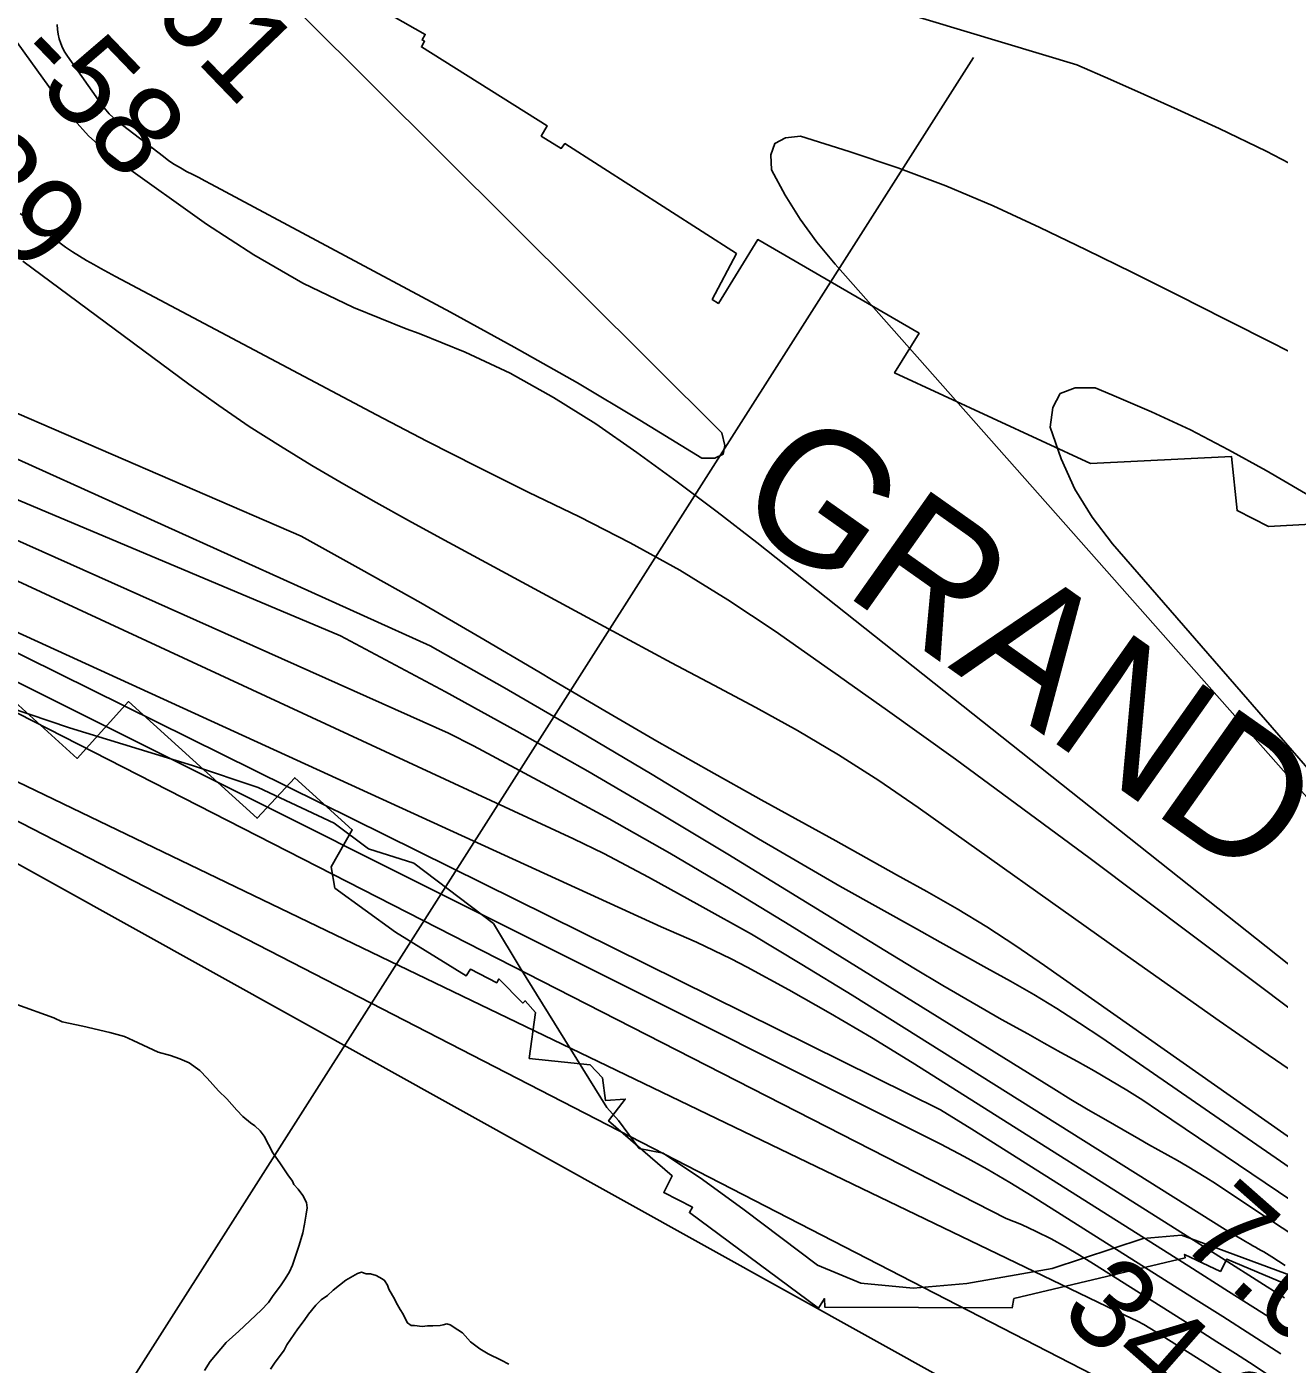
# Model space of a CAD drawing. Extents: x 3263578 to 3301413, y 764927 to 798602.
# Drawn here: x 3278134 to 3279070, y 785102 to 786102 of the extents above; entities that cross this region are included whole.
import ezdxf

# ---------------------------------------------------------------- set-up
doc = ezdxf.new("R2010")
doc.units = 0
for name, color, linetype in [('V-RIVR-EDGE', 7, 'Continuous'), ('V-RIVR-RANG', 7, 'Continuous'), ('V-RRAP-RVMT', 7, 'Continuous'), ('V-RRAP-RVMT-IDEN', 7, 'Continuous'), ('V-SITE-VEGE', 7, 'Continuous'), ('V-TOPO-DPTH', 7, 'Continuous'), ('V-TOPO-MAJR', 7, 'Continuous'), ('V-TOPO-MINR', 7, 'Continuous'), ('V-TOPO-WATR', 7, 'Continuous')]:
    doc.layers.add(name, color=color, linetype=linetype)

msp = doc.modelspace()

# ---------------------------------------------------------------- linework, layer by layer
at = {"layer": 'V-RIVR-EDGE'}
for points in [[(3278074.7, 785608), (3278165.5, 785577.4), (3278257.6, 785549.3), (3278306.7, 785532.7), (3278363.5, 785506), (3278389.1, 785486.9), (3278423, 785476.3), (3278482.5, 785431), (3278502.4, 785397.9), (3278540.5, 785337), (3278567.3, 785293.4), (3278576, 785283.8), (3278591.6, 785262.9)], [(3278591.6, 785262.9), (3278609.4, 785259.4), (3278638.9, 785239.8), (3278670.1, 785217.1), (3278724.8, 785175.7), (3278757.4, 785162.1), (3278796.5, 785158.5), (3278836.5, 785161.9), (3278900.4, 785173.1), (3278968.3, 785195.5), (3278997, 785198), (3279024.3, 785188), (3279144.2, 785143.8)]]:
    msp.add_lwpolyline(points, dxfattribs=at)
at = {"layer": 'V-RIVR-RANG'}
msp.add_line((3278164.9, 785015.8), (3278841.6, 786078.7), dxfattribs=at)
at = {"layer": 'V-RRAP-RVMT'}
for points in [[(3278375.6, 786127.6), (3278431.5, 786095.9), (3278429.2, 786091.8), (3278431, 786090.8), (3278428.7, 786086.5), (3278522.8, 786027.4), (3278518.3, 786019.9), (3278533.2, 786010.6), (3278536, 786014.2), (3278664.3, 785932), (3278646.2, 785897.7), (3278650.8, 785894.7), (3278680.2, 785942.5), (3278800.8, 785872.4), (3278782.5, 785842.8), (3278929.1, 785775), (3279034.6, 785780.2), (3279038.7, 785739.8), (3279062.1, 785727.9), (3279152.7, 785733)], [(3279091.8, 785154.5), (3279030.9, 785180.2), (3279026.2, 785170.9), (3278999.4, 785183.7), (3278999.9, 785181.2), (3278871.8, 785150.7), (3278870.5, 785143.8), (3278730.4, 785144.2), (3278730, 785150.7), (3278725.7, 785143.5), (3278629.1, 785214.9), (3278631.4, 785218.9), (3278609.9, 785229.9), (3278616.2, 785242.4), (3278568.6, 785283.5), (3278581.1, 785299.8), (3278566.4, 785298.7), (3278564.2, 785315.7), (3278554.8, 785325.3), (3278509.3, 785330.2), (3278514, 785364.5), (3278506.2, 785373.3), (3278504.4, 785371.6), (3278486.6, 785389.7), (3278485, 785386.8), (3278465.3, 785396.9), (3278462.2, 785392), (3278409.4, 785424.7), (3278363.9, 785457.6), (3278361.2, 785473.5), (3278376.9, 785501.2), (3278333.9, 785540.1), (3278305.8, 785509.8), (3278209.6, 785597), (3278171.2, 785554.5), (3278075, 785641.8)]]:
    msp.add_lwpolyline(points, dxfattribs=at)
at = {"layer": 'V-SITE-VEGE'}
for points in [[(3278126.1, 785370.6), (3278153.7, 785360.6), (3278160, 785357.6), (3278175.5, 785354.3), (3278195.7, 785349.7), (3278206.7, 785346.5), (3278213, 785343.5), (3278231.9, 785334.9), (3278241.1, 785332.3), (3278248, 785329.8), (3278254.9, 785326.8), (3278262.9, 785321.3), (3278268.5, 785315.4), (3278277, 785305.9), (3278283.2, 785299.9), (3278290.6, 785291.6), (3278295.1, 785286.9), (3278300.8, 785282.1), (3278304.2, 785279.7), (3278308.2, 785276.1), (3278311, 785272), (3278317.6, 785259.6), (3278323.2, 785251.4), (3278328.8, 785243.1), (3278332.2, 785238.4), (3278333.3, 785236), (3278336.6, 785232.5)], [(3278336.6, 785232.5), (3278340, 785227.8), (3278342.8, 785222.5), (3278343.3, 785218.4), (3278342.6, 785213.8), (3278341.2, 785206.3), (3278339.9, 785199.9), (3278337.3, 785190.7), (3278332.3, 785175.7), (3278329.9, 785170.6), (3278326.8, 785165.4), (3278323.2, 785160.3), (3278317.8, 785152.9), (3278314.2, 785147.8), (3278308.9, 785142.1), (3278292.2, 785126.3), (3278282.7, 785117.8), (3278270.8, 785103.6), (3278266.5, 785096.8)], [(3278315.9, 785097.8), (3278318.9, 785102.4), (3278326.1, 785112.1), (3278327.9, 785116.1), (3278336.3, 785128.1), (3278341.1, 785134.3), (3278344.2, 785138.9), (3278349.6, 785145.7), (3278353.7, 785149.7), (3278358.4, 785153), (3278362.6, 785157), (3278372.1, 785164.3), (3278380.9, 785169.3), (3278383.8, 785170.4), (3278387.3, 785169.1), (3278390.7, 785169.1), (3278394.8, 785167.8), (3278399.4, 785165.4), (3278401.1, 785164.2), (3278403.3, 785160.6), (3278404.4, 785157.7), (3278408.8, 785150), (3278409.9, 785147.7), (3278412.7, 785142.4), (3278414.9, 785138.9), (3278417.1, 785134.7), (3278418.3, 785132.4), (3278421.1, 785130.6), (3278423.4, 785130.5), (3278429.2, 785129.8), (3278433.3, 785130.3), (3278437.3, 785130.2), (3278442.6, 785130.6), (3278444.9, 785131.1), (3278447.8, 785131.7), (3278450.1, 785131), (3278455.8, 785127.4), (3278459.3, 785125), (3278465.5, 785118.4), (3278472.3, 785113.1), (3278478.6, 785109.4), (3278488.3, 785104.5), (3278494, 785101.5)]]:
    msp.add_lwpolyline(points, dxfattribs=at)
at = {"layer": 'V-TOPO-DPTH'}
for points in [[(3278128.7, 785961.9), (3278157.6, 785940.5), (3278162.6, 785936.9), (3278167.7, 785933.4), (3278173, 785930.1), (3278178.3, 785926.9), (3278183.6, 785923.8), (3278189, 785920.8), (3278194.5, 785917.8), (3278199.9, 785914.9), (3278395.1, 785811.5), (3278432.7, 785791.8), (3278470.6, 785772.5), (3278508.6, 785753.6), (3278546.8, 785735.1), (3278584.7, 785715.8), (3278621.8, 785695.4), (3278657.8, 785673.1), (3278693.1, 785649.7), (3278726, 785626.6), (3278777.1, 785590.4), (3278828, 785553.9), (3278878.5, 785516.9), (3278928.7, 785479.6), (3279162.7, 785304)], [(3279162.7, 785304), (3278928.7, 785479.6), (3278878.5, 785516.9), (3278828, 785553.9), (3278777.1, 785590.4), (3278726, 785626.6), (3278693.1, 785649.7), (3278657.8, 785673.1), (3278621.8, 785695.4), (3278584.7, 785715.8), (3278546.8, 785735.1), (3278508.6, 785753.6), (3278470.6, 785772.5), (3278432.7, 785791.8), (3278395.1, 785811.5), (3278199.9, 785914.9), (3278194.5, 785917.8), (3278189, 785920.8), (3278183.6, 785923.8), (3278178.3, 785926.9), (3278173, 785930.1), (3278167.7, 785933.4), (3278162.6, 785936.9), (3278157.6, 785940.5), (3278128.7, 785961.9)], [(3279098.7, 785307.7), (3279062, 785333), (3279025.3, 785358.4), (3278988.8, 785384), (3278952.4, 785409.7), (3278800.1, 785517.9), (3278770.7, 785538), (3278740.7, 785557.2), (3278710, 785575.3), (3278678.8, 785592.6), (3278647.3, 785609.4), (3278615.8, 785626.1), (3278584.4, 785643), (3278552.9, 785659.9), (3278443.2, 785719.2), (3278418.9, 785732.5), (3278394.8, 785745.9), (3278370.7, 785759.6), (3278346.8, 785773.5), (3278323.2, 785787.9), (3278299.9, 785802.7), (3278277.1, 785818.3), (3278254.7, 785834.4), (3278130.7, 785926.4)], [(3279098.7, 785307.7), (3279062, 785333), (3279025.3, 785358.4), (3278988.8, 785384), (3278952.4, 785409.7), (3278800.1, 785517.9), (3278770.7, 785538), (3278740.7, 785557.2), (3278710, 785575.3), (3278678.8, 785592.6), (3278647.3, 785609.4), (3278615.8, 785626.1), (3278584.4, 785643), (3278552.9, 785659.9), (3278443.2, 785719.2), (3278418.9, 785732.5), (3278394.8, 785745.9), (3278370.7, 785759.6), (3278346.8, 785773.5), (3278323.2, 785787.9), (3278299.9, 785802.7), (3278277.1, 785818.3), (3278254.7, 785834.4), (3278130.7, 785926.4)], [(3278020.5, 785858.4), (3278338.7, 785720.6), (3278383.6, 785695.9), (3278428.2, 785670.9), (3278472.4, 785645.3), (3278516.5, 785619.3), (3278527.3, 785612.8), (3278565.9, 785590), (3278604.6, 785567.5), (3278643.6, 785545.4), (3278682.8, 785523.5), (3278715.8, 785505.4), (3278738.5, 785492.9), (3278761.3, 785480.3), (3278784, 785467.6), (3278806.7, 785455), (3278829.2, 785442), (3278851.4, 785428.5), (3278873.2, 785414.4), (3278894.7, 785399.8), (3279137.2, 785229.4)], [(3278020.5, 785858.4), (3278338.7, 785720.6), (3278383.6, 785695.9), (3278428.2, 785670.9), (3278472.4, 785645.3), (3278516.5, 785619.3), (3278527.3, 785612.8), (3278565.9, 785590), (3278604.6, 785567.5), (3278643.6, 785545.4), (3278682.8, 785523.5), (3278715.8, 785505.4), (3278738.5, 785492.9), (3278761.3, 785480.3), (3278784, 785467.6), (3278806.7, 785455), (3278829.2, 785442), (3278851.4, 785428.5), (3278873.2, 785414.4), (3278894.7, 785399.8), (3279137.2, 785229.4)], [(3279079.6, 785223.8), (3278979.9, 785291.1), (3278968.1, 785298.9), (3278956.1, 785306.5), (3278944, 785313.8), (3278931.7, 785320.9), (3278919.3, 785327.8), (3278906.9, 785334.7), (3278894.5, 785341.6), (3278882.1, 785348.5), (3278862.6, 785359.4), (3278840.6, 785372), (3278818.6, 785384.7), (3278796.8, 785397.6), (3278775.2, 785410.8), (3278657.7, 785482.9), (3278605.5, 785514.3), (3278553, 785545.1), (3278500, 785574.9), (3278446.6, 785604.2), (3278368.2, 785646.2), (3277976.7, 785810.9)], [(3279079.6, 785223.8), (3278979.9, 785291.1), (3278968.1, 785298.9), (3278956.1, 785306.5), (3278944, 785313.8), (3278931.7, 785320.9), (3278919.3, 785327.8), (3278906.9, 785334.7), (3278894.5, 785341.6), (3278882.1, 785348.5), (3278862.6, 785359.4), (3278840.6, 785372), (3278818.6, 785384.7), (3278796.8, 785397.6), (3278775.2, 785410.8), (3278657.7, 785482.9), (3278605.5, 785514.3), (3278553, 785545.1), (3278500, 785574.9), (3278446.6, 785604.2), (3278368.2, 785646.2), (3277976.7, 785810.9)], [(3277930.9, 785777.7), (3278542.5, 785494.5), (3278565, 785483.4), (3278598.4, 785465.7), (3278637, 785444.6), (3278675.4, 785423), (3278713.2, 785400.5), (3278750.8, 785377.5), (3279029.8, 785202.3), (3279033.5, 785200), (3279037.3, 785197.8), (3279041.1, 785195.5), (3279044.9, 785193.3), (3279048.4, 785191.4), (3279050.4, 785190.2), (3279052.5, 785189), (3279054.5, 785187.9), (3279056.6, 785186.7), (3279058.7, 785185.5), (3279060.7, 785184.3), (3279062.7, 785183.1), (3279064.7, 785181.8), (3279074.5, 785175.5)], [(3277930.9, 785777.7), (3278542.5, 785494.5), (3278565, 785483.4), (3278598.4, 785465.7), (3278637, 785444.6), (3278675.4, 785423), (3278713.2, 785400.5), (3278750.8, 785377.5), (3279029.8, 785202.3), (3279033.5, 785200), (3279037.3, 785197.8), (3279041.1, 785195.5), (3279044.9, 785193.3), (3279048.4, 785191.4), (3279050.4, 785190.2), (3279052.5, 785189), (3279054.5, 785187.9), (3279056.6, 785186.7), (3279058.7, 785185.5), (3279060.7, 785184.3), (3279062.7, 785183.1), (3279064.7, 785181.8), (3279074.5, 785175.5)], [(3280108.8, 784602.6), (3280105.1, 784605.7), (3280097, 784612), (3280088.7, 784618), (3280032.8, 784656.3), (3280020.2, 784664.7), (3280007.6, 784672.8), (3279994.7, 784680.5), (3279981.7, 784688.1), (3279968.5, 784695.3), (3279955.3, 784702.4), (3279941.9, 784709.3), (3279928.5, 784716.1), (3279905.2, 784727.6), (3279879.7, 784739.3), (3279174.8, 785064.2), (3279120.7, 785099.3), (3279091.3, 785118.3), (3279061.8, 785137.2), (3279032.2, 785156), (3279002.6, 785174.8), (3278840.2, 785277.4), (3278816.8, 785291.7), (3277913, 785738.9)]]:
    msp.add_lwpolyline(points, dxfattribs=at)
at = {"layer": 'V-TOPO-MAJR'}
for points in [[(3279536.3, 785673.9), (3279530.6, 785678), (3279525, 785682.1), (3279289.2, 785861), (3279257.9, 785884.2), (3279226.3, 785906.9), (3279194.1, 785929), (3279161.7, 785950.6), (3279128.6, 785971.1), (3279094.9, 785990.6), (3279060.4, 786008.5), (3279025.3, 786025.5), (3278994.2, 786039.7), (3278969.2, 786051), (3278944, 786062.2), (3278918.8, 786073.2), (3278419.2, 786223.7)], [(3278044, 786204.1), (3278158.9, 786044.5), (3278169, 786031.9), (3278179.8, 786020), (3278191.7, 786009.3), (3278204.4, 785999.3), (3278267.9, 785954.1), (3278303.3, 785931), (3278339.9, 785909.9), (3278378, 785891.8), (3278417.2, 785875.8), (3278426.9, 785872.3), (3278461.4, 785858.4), (3278495.1, 785842.7), (3278527.5, 785824.5), (3278559, 785804.7), (3278589.7, 785783.3), (3278620, 785761.4), (3278649.9, 785738.9), (3278679.5, 785715.9), (3279192.9, 785308.7)], [(3277841.3, 785674.3), (3278954.6, 785138.3), (3278959.4, 785136.1), (3278964.1, 785133.7), (3278968.8, 785131.2), (3278973.4, 785128.5), (3278978, 785125.7), (3279013, 785103.6), (3279019.2, 785099.6), (3279025.4, 785095.7), (3279031.5, 785091.7), (3279037.7, 785087.7), (3279961.1, 784591.1), (3280018.6, 784566.2), (3280039, 784555.3), (3280049.3, 784548.2)]]:
    msp.add_lwpolyline(points, dxfattribs=at)
at = {"layer": 'V-TOPO-MINR'}
for points in [[(3276581.6, 787830.9), (3276665.1, 787735.6), (3277232.8, 786656.4), (3277234.3, 786653.6), (3277235.7, 786650.8), (3277237.2, 786648), (3277238.7, 786645.3), (3277793.7, 785682.2), (3277809, 785664.6), (3277825.7, 785648.5), (3277843.3, 785633.3), (3278947.3, 785019.5), (3278951.5, 785017.8), (3278955.6, 785015.9), (3278959.7, 785013.8), (3278963.6, 785011.4), (3280019.9, 784521.3)], [(3278244.1, 785998.6), (3278248.6, 785996), (3278253.1, 785993.5), (3278257.7, 785991.2), (3278262.3, 785988.9), (3278266.8, 785986.5), (3278271.4, 785984), (3278450.5, 785888.2), (3278498.1, 785862.1), (3278545.3, 785835.3), (3278592, 785807.5), (3278638.3, 785779.1), (3278648, 785779.1), (3278654.3, 785781.9), (3278655.5, 785788.6), (3278653.3, 785798), (3278339.6, 786110.3)], [(3278156.2, 786103.2), (3278156.5, 786099.6), (3278157, 786096), (3278157.8, 786092.5), (3278158.9, 786089.1), (3278160.3, 786085.8), (3278162, 786082.6), (3278163.9, 786079.6), (3278190.2, 786042.5), (3278192.6, 786039.4), (3278195.2, 786036.5), (3278198.1, 786033.8), (3278201, 786031.3), (3278235.7, 786004.5), (3278239.9, 786001.4), (3278244.1, 785998.6)], [(3279100.9, 785846.8), (3279065.9, 785864.7), (3279030.8, 785882.5), (3279029.2, 785883.3), (3278994.8, 785900.6), (3278960.4, 785917.8), (3278925.8, 785934.8), (3278891.2, 785951.6), (3278856.3, 785967.6), (3278820.9, 785982.6), (3278784.9, 785996), (3278748.5, 786008.4), (3278712.2, 786019.9), (3278700.9, 786018.6), (3278692.9, 786014.4), (3278690, 786005.9), (3278690.5, 785994.5), (3278700.7, 785975.8), (3278711.9, 785957.7), (3278724.5, 785940.6), (3278738, 785924.1), (3279215.2, 785385)], [(3278128.7, 785961.9), (3278157.6, 785940.5), (3278162.6, 785936.9), (3278167.7, 785933.4), (3278173, 785930.1), (3278178.3, 785926.9), (3278183.6, 785923.8), (3278189, 785920.8), (3278194.5, 785917.8), (3278199.9, 785914.9), (3278395.1, 785811.5), (3278432.7, 785791.8), (3278470.6, 785772.5), (3278508.6, 785753.6), (3278546.8, 785735.1), (3278584.7, 785715.8), (3278621.8, 785695.4), (3278657.8, 785673.1), (3278693.1, 785649.7), (3278726, 785626.6), (3278777.1, 785590.4), (3278828, 785553.9), (3278878.5, 785516.9), (3278928.7, 785479.6), (3279162.7, 785304)], [(3278130.7, 785926.4), (3278254.7, 785834.4), (3278277.1, 785818.3), (3278299.9, 785802.7), (3278323.2, 785787.9), (3278346.8, 785773.5), (3278370.7, 785759.6), (3278394.8, 785745.9), (3278418.9, 785732.5), (3278443.2, 785719.2), (3278552.9, 785659.9), (3278584.4, 785643), (3278615.8, 785626.1), (3278647.3, 785609.4), (3278678.8, 785592.6), (3278710, 785575.3), (3278740.7, 785557.2), (3278770.7, 785538), (3278800.1, 785517.9), (3278952.4, 785409.7), (3278988.8, 785384), (3279025.3, 785358.4), (3279062, 785333), (3279098.7, 785307.7)], [(3278020.5, 785858.4), (3278338.7, 785720.6), (3278383.6, 785695.9), (3278428.2, 785670.9), (3278472.4, 785645.3), (3278516.5, 785619.3), (3278527.3, 785612.8), (3278565.9, 785590), (3278604.6, 785567.5), (3278643.6, 785545.4), (3278682.8, 785523.5), (3278715.8, 785505.4), (3278738.5, 785492.9), (3278761.3, 785480.3), (3278784, 785467.6), (3278806.7, 785455), (3278829.2, 785442), (3278851.4, 785428.5), (3278873.2, 785414.4), (3278894.7, 785399.8), (3279137.2, 785229.4)], [(3277988.4, 785840.5), (3278435.1, 785638.8), (3278490.9, 785607.4), (3278546.2, 785575.2), (3278601.2, 785542.4), (3278650.4, 785512.6), (3278680.7, 785494.4), (3278711.1, 785476.6), (3278741.7, 785459), (3278772.4, 785441.7), (3278799, 785427), (3278816.5, 785417.2), (3278834.1, 785407.5), (3278851.6, 785397.7), (3278869.2, 785387.9), (3278886.6, 785377.9), (3278903.8, 785367.5), (3278920.7, 785356.7), (3278937.4, 785345.6), (3279109.7, 785226.8)], [(3279280.8, 785641), (3279060.3, 785769.7), (3279032.2, 785785.3), (3279003.7, 785800.1), (3278974.6, 785813.7), (3278945.1, 785826.5), (3278932.4, 785831.7), (3278917.6, 785831.6), (3278906.4, 785827.3), (3278900.8, 785816.8), (3278898.9, 785802.1), (3278907.1, 785778.5), (3278917.3, 785755.9), (3278930.4, 785735), (3278945.5, 785715), (3279232.4, 785385)], [(3277976.7, 785810.9), (3278368.2, 785646.2), (3278446.6, 785604.2), (3278500, 785574.9), (3278553, 785545.1), (3278605.5, 785514.3), (3278657.7, 785482.9), (3278775.2, 785410.8), (3278796.8, 785397.6), (3278818.6, 785384.7), (3278840.6, 785372), (3278862.6, 785359.4), (3278882.1, 785348.5), (3278894.5, 785341.6), (3278906.9, 785334.7), (3278919.3, 785327.8), (3278931.7, 785320.9), (3278944, 785313.8), (3278956.1, 785306.5), (3278968.1, 785298.9), (3278979.9, 785291.1), (3279079.6, 785223.8)], [(3277954, 785794.5), (3278429.9, 785582), (3278449, 785573.3), (3278467.7, 785564), (3278523, 785534.4), (3278569, 785509.3), (3278614.5, 785483.6), (3278659.6, 785457), (3278704.3, 785429.9), (3278901.6, 785307.4), (3278914.4, 785299.5), (3278927.3, 785291.8), (3278940.4, 785284.2), (3278953.4, 785276.7), (3278965.3, 785270), (3278972.5, 785265.9), (3278979.7, 785261.9), (3278986.9, 785257.8), (3278994.1, 785253.8), (3279001.3, 785249.7), (3279008.4, 785245.5), (3279015.4, 785241.1), (3279022.4, 785236.6), (3279056.3, 785214), (3279080.3, 785198.3)], [(3277913, 785738.9), (3278816.8, 785291.7), (3278840.2, 785277.4), (3279002.6, 785174.8), (3279032.2, 785156), (3279061.8, 785137.2), (3279091.3, 785118.3), (3279120.7, 785099.3), (3279174.8, 785064.2), (3279879.7, 784739.3), (3279905.2, 784727.6), (3279928.5, 784716.1), (3279941.9, 784709.3), (3279955.3, 784702.4), (3279968.5, 784695.3), (3279981.7, 784688.1), (3279994.7, 784680.5), (3280007.6, 784672.8), (3280020.2, 784664.7), (3280032.8, 784656.3), (3280088.7, 784618), (3280097, 784612), (3280105.1, 784605.7), (3280108.8, 784602.6)], [(3277945.6, 785731.5), (3278607.9, 785428.6), (3278634.3, 785417.2), (3278660.2, 785404.6), (3278672.2, 785398.4), (3278703.5, 785381.4), (3278734.6, 785363.9), (3278765.3, 785345.8), (3278795.6, 785327.1), (3279031.8, 785178.1), (3279053, 785164.7), (3279074.1, 785151.3)], [(3277913.6, 785717.9), (3278817.1, 785266.2), (3278834.5, 785257), (3278851.7, 785247.5), (3278868.7, 785237.5), (3278885.4, 785227.2), (3279006.1, 785151), (3279027.9, 785137.2), (3279049.6, 785123.3), (3279071.3, 785109.4)], [(3277914.2, 785696.9), (3278866, 785210.4), (3278877.4, 785206), (3278888.5, 785200.9), (3278899.5, 785195.2), (3278910.3, 785189.3), (3278920.9, 785183.1), (3278931.4, 785176.7), (3279009.5, 785127.2), (3279023.5, 785118.4), (3279037.4, 785109.5), (3279051.4, 785100.5), (3279065.2, 785091.5), (3280027.7, 784629.4)], [(3277842.3, 785653.8), (3279023.6, 785046), (3279053.2, 785033.2), (3279082.3, 785019), (3279111.1, 785004.2), (3279139.3, 784988.4), (3279167.2, 784972), (3279205.8, 784948.2), (3279252.7, 784919.2), (3280008.5, 784548.1), (3280024.7, 784541.7), (3280036, 784536)]]:
    msp.add_lwpolyline(points, dxfattribs=at)
at = {"layer": 'V-TOPO-WATR'}
msp.add_lwpolyline([(3277930.9, 785777.7), (3278542.5, 785494.5), (3278565, 785483.4), (3278598.4, 785465.7), (3278637, 785444.6), (3278675.4, 785423), (3278713.2, 785400.5), (3278750.8, 785377.5), (3279029.8, 785202.3), (3279033.5, 785200), (3279037.3, 785197.8), (3279041.1, 785195.5), (3279044.9, 785193.3), (3279048.4, 785191.4), (3279050.4, 785190.2), (3279052.5, 785189), (3279054.5, 785187.9), (3279056.6, 785186.7), (3279058.7, 785185.5), (3279060.7, 785184.3), (3279062.7, 785183.1), (3279064.7, 785181.8), (3279074.5, 785175.5)], dxfattribs=at)

# ---------------------------------------------------------------- texts
at = {"layer": 'V-RIVR-RANG'}
for s, rotation, p in [('-61', 313.9212, (3278203.8, 786134)), ('-58', 313.9212, (3278120.2, 786076.6)), ('-39', 313.9212, (3278047.6, 786007.9)), ('7.0', 318.6383, (3278993.1, 785193.1)), ('34.3', 318.6383, (3278904.5, 785138))]:
    msp.add_text(s, height=67, rotation=rotation, dxfattribs=at).set_placement(p)
at = {"layer": 'V-RRAP-RVMT-IDEN'}
msp.add_text('GRAND', height=100, rotation=324.7476, dxfattribs=at).set_placement((3278658, 785738.7))

doc.saveas('drawing.dxf')
